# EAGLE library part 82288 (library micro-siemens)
MICROPROCESSOR/PERIPHERAL DEVICE
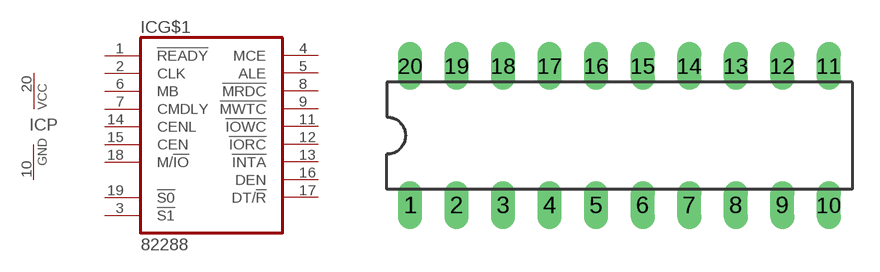
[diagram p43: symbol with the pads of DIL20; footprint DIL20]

Designator prefix IC; gates G$1=82288 P=VCCGND

## 82288 (OC_FARNELL: unknown; OC_NEWARK: unknown)  [DIL20]
1  G$1:!READY  in
2  G$1:CLK  in
3  G$1:!S1  in
4  G$1:MCE  out
5  G$1:ALE  out
6  G$1:MB  in
7  G$1:CMDLY  in
8  G$1:!MRDC  out
9  G$1:!MWTC  out
10  P:GND  pwr
11  G$1:!IOWC  out
12  G$1:!IORC  out
13  G$1:!INTA  out
14  G$1:CENL  in
15  G$1:CEN  in
16  G$1:DEN  out
17  G$1:DT/!R  out
18  G$1:M/!IO  in
19  G$1:!S0  in
20  P:VCC  pwr

## Footprint DIL20 (pad centres in mm)
Dual In Line Package
drill 0.813 long: 1 -11.43,-3.81; 2 -8.89,-3.81; 3 -6.35,-3.81; 4 -3.81,-3.81; 5 -1.27,-3.81; 6 1.27,-3.81; 7 3.81,-3.81; 8 6.35,-3.81; 9 8.89,-3.81; 10 11.43,-3.81; 11 11.43,3.81; 12 8.89,3.81; 13 6.35,3.81; 14 3.81,3.81; 15 1.27,3.81; 16 -1.27,3.81; 17 -3.81,3.81; 18 -6.35,3.81; 19 -8.89,3.81; 20 -11.43,3.81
